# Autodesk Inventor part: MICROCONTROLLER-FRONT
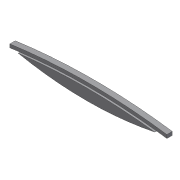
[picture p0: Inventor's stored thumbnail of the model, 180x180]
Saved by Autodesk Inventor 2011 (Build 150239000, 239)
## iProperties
Created: 2010-06
Part Number: MICROCONTROLLER-FRONT
Document SubType Name: Modeling
Designer: kurdi
Density: 1 g/cm^3
Author: kurdi
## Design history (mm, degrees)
sketch "Sketch1"
  geometry: L1 (-19.284, 0)-(19.284, 0); A1 r 157.023 centre (0, -155.834) between (19.284, 0) and (-19.284, 0); A2 r 96.507 centre (0, 94.561) between (-19.284, 0) and (19.284, 0); 2 further points
  constraints: 4 point on circle, 2 centre point, 2 end point, 1 coincident, 1 horizontal, 1 midpoint
  dimensions: "d0" = 38.56736 distance of L1.start L1.end; "d1" = 157.0228 radius of A1; "d2" = 96.50679 radius of A2
extrude "Extrusion1" new body sketch "Sketch1" distance "d3" = 0.508; taper "d4" = 0 deg
sketch "Sketch2"
  geometry: L1 (-22.149, 0.594)-(-22.149, -0.381); L2 (22.149, 0.594)-(22.149, -0.381); A1 r 157.023 centre (0, -155.834) between (19.284, 0) and (-19.284, 0) reference; A2 r 96.507 centre (0, 94.561) between (-19.284, 0) and (19.284, 0) reference; A3 r 157.988 centre (0, -155.834) between (22.149, 0.594) and (-22.149, 0.594); A4 r 157.023 centre (0, -155.834) between (-19.284, 0) and (-22.149, -0.381); A5 r 157.023 centre (0, -155.834) between (22.149, -0.381) and (19.284, 0); 2 further points
  constraints: 9 point on circle, 4 end point, 3 centre point, 3 concentric, 2 parallel, 1 vertical, 1 vertical alignment
  dimensions: "d5" = 44.2976 distance between parallel lines of L2 L1; "d6" = 157.988 radius of A3
extrude "Extrusion2" join sketch "Sketch2" distance "d7" = 1.524; taper "d8" = 0 deg
body "Solid1"
